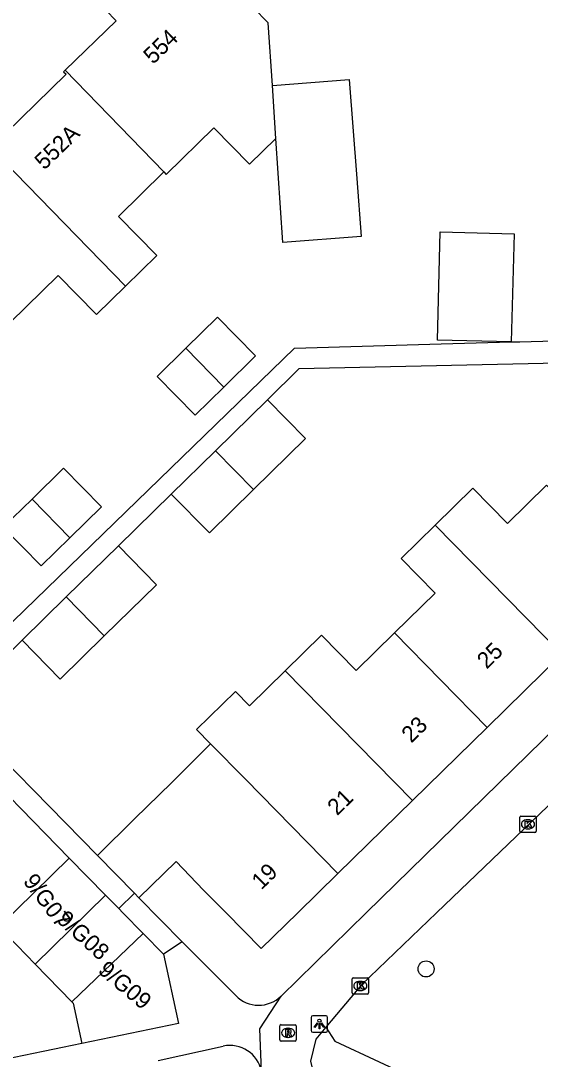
# Model space of a CAD drawing. Extents: x 162880 to 165536, y 384011 to 385179.
# Drawn here: x 164047.4 to 164079, y 384241.1 to 384304.3 of the extents above; entities that cross this region are included whole.
import ezdxf

# ---------------------------------------------------------------- set-up
doc = ezdxf.new("R2010")
doc.units = 0
for name, color, linetype in [('IMGEO_Boom', 7, 'Continuous'), ('IMGEO_Kolk', 7, 'Continuous'), ('IMGEO_Lichtpunt', 7, 'Continuous'), ('IMGEO_Pand', 7, 'Continuous'), ('IMGEO_Pand_nummerreeks', 7, 'Continuous'), ('IMGEO_Rijbaan_lokaal_open', 7, 'Continuous'), ('IMGEO_Rioolput', 7, 'Continuous'), ('IMGEO_Voetpad_halfverhard', 7, 'Continuous'), ('IMGEO_Voetpad_open', 7, 'Continuous')]:
    doc.layers.add(name, color=color, linetype=linetype)

msp = doc.modelspace()

# ---------------------------------------------------------------- linework, layer by layer
at = {"layer": 'IMGEO_Boom'}
msp.add_circle((164072.025, 384246.586), 0.489, dxfattribs=at)
at = {"layer": 'IMGEO_Kolk'}
for p, q in [((164077.725, 384254.97), (164077.725, 384255.822)), ((164077.8, 384255.896), (164078.652, 384255.896)), ((164078.213, 384255.676), (164078.238, 384255.676)), ((164078.726, 384255.822), (164078.726, 384254.97)), ((164078.236, 384255.116), (164078.211, 384255.116)), ((164078.652, 384254.896), (164077.8, 384254.896)), ((164067.522, 384245.125), (164067.522, 384245.977)), ((164067.597, 384246.051), (164068.449, 384246.051)), ((164068.01, 384245.831), (164068.035, 384245.831)), ((164068.523, 384245.977), (164068.523, 384245.125)), ((164068.449, 384245.051), (164067.597, 384245.051)), ((164068.033, 384245.271), (164068.008, 384245.271))]:
    msp.add_line(p, q, dxfattribs=at)
for points in [[(164077.725, 384254.97), (164077.725, 384255.822)], [(164077.8, 384255.896), (164078.652, 384255.896)], [(164078.726, 384255.822), (164078.726, 384254.97)], [(164078.046, 384255.596), (164078.169, 384255.596), (164078.169, 384255.445), (164078.299, 384255.596), (164078.463, 384255.596), (164078.317, 384255.445), (164078.47, 384255.196), (164078.318, 384255.196), (164078.233, 384255.36), (164078.169, 384255.293), (164078.169, 384255.196), (164078.046, 384255.196), (164078.046, 384255.596)], [(164078.652, 384254.896), (164077.8, 384254.896)], [(164067.522, 384245.125), (164067.522, 384245.977)], [(164067.597, 384246.051), (164068.449, 384246.051)], [(164067.843, 384245.751), (164067.966, 384245.751), (164067.966, 384245.6), (164068.096, 384245.751), (164068.26, 384245.751), (164068.114, 384245.6), (164068.267, 384245.351), (164068.115, 384245.351), (164068.03, 384245.515), (164067.966, 384245.448), (164067.966, 384245.351), (164067.843, 384245.351), (164067.843, 384245.751)], [(164068.523, 384245.977), (164068.523, 384245.125)], [(164068.449, 384245.051), (164067.597, 384245.051)]]:
    msp.add_lwpolyline(points, dxfattribs=at)
for centre, start, end in [((164077.802, 384255.82), 91.55205, 178.44795), ((164077.802, 384255.82), 91.55205, 178.44795), ((164078.65, 384255.82), 1.55205, 88.44795), ((164078.65, 384255.82), 1.55205, 88.44795), ((164077.802, 384254.972), 181.55205, 268.44795), ((164077.802, 384254.972), 181.55205, 268.44795), ((164078.65, 384254.972), 271.55205, 358.44795), ((164078.65, 384254.972), 271.55205, 358.44795), ((164067.599, 384245.975), 91.55205, 178.44795), ((164067.599, 384245.975), 91.55205, 178.44795), ((164068.447, 384245.975), 1.55205, 88.44795), ((164068.447, 384245.975), 1.55205, 88.44795), ((164067.599, 384245.127), 181.55205, 268.44795), ((164067.599, 384245.127), 181.55205, 268.44795), ((164068.447, 384245.127), 271.55205, 358.44795), ((164068.447, 384245.127), 271.55205, 358.44795)]:
    msp.add_arc(centre, 0.0765, start, end, dxfattribs=at)
for centre, major_axis, ratio, start_param, end_param in [((164078.212, 384255.396), (-0.387, 0.002), 0.722429, 4.712389, 7.853982), ((164078.237, 384255.396), (-0.39, 0.002), 0.717154, 1.570796, 4.712389), ((164068.009, 384245.551), (-0.387, 0.002), 0.722429, 4.712389, 7.853982), ((164068.034, 384245.551), (-0.39, 0.002), 0.717154, 1.570796, 4.712389)]:
    msp.add_ellipse(centre, major_axis=major_axis, ratio=ratio, start_param=start_param, end_param=end_param, dxfattribs=at)
at = {"layer": 'IMGEO_Lichtpunt'}
for p, q in [((164065.034, 384243.637), (164065.034, 384242.83)), ((164065.034, 384243.637), (164065.034, 384242.83)), ((164065.936, 384243.732), (164065.128, 384243.732)), ((164065.936, 384243.732), (164065.128, 384243.732)), ((164066.03, 384242.83), (164066.03, 384243.637)), ((164066.03, 384242.83), (164066.03, 384243.637)), ((164065.128, 384242.736), (164065.936, 384242.736)), ((164065.128, 384242.736), (164065.936, 384242.736))]:
    msp.add_line(p, q, dxfattribs=at)
for points in [[(164065.408, 384243.301), (164065.447, 384243.273), (164065.259, 384243.011), (164065.221, 384243.038), (164065.408, 384243.301)], [(164065.51, 384243.253), (164065.557, 384243.253), (164065.557, 384242.931), (164065.51, 384242.931), (164065.51, 384243.253)], [(164065.62, 384243.273), (164065.658, 384243.3), (164065.845, 384243.038), (164065.806, 384243.01), (164065.62, 384243.273)]]:
    msp.add_lwpolyline(points, dxfattribs=at)
msp.add_circle((164065.533, 384243.435), 0.0994, dxfattribs=at)
for centre, start, end in [((164065.128, 384243.637), 90, 180), ((164065.128, 384243.637), 90, 180), ((164065.936, 384243.637), 0, 90), ((164065.936, 384243.637), 0, 90), ((164065.128, 384242.83), 180, 270), ((164065.128, 384242.83), 180, 270), ((164065.936, 384242.83), 270, 0), ((164065.936, 384242.83), 270, 360)]:
    msp.add_arc(centre, 0.0946, start, end, dxfattribs=at)
at = {"layer": 'IMGEO_Pand'}
for points in [[(164062.668, 384300.404), (164062.417, 384304.214), (164061.503, 384305.153), (164058.017, 384308.737), (164055.073, 384305.874), (164054.294, 384306.679), (164052.538, 384304.98), (164053.169, 384304.345), (164050.068, 384301.337)], [(164050.068, 384301.337), (164049.966, 384301.238), (164050.119, 384301.08), (164045.521, 384296.61)], [(164050.068, 384301.337), (164056.064, 384295.138)], [(164062.668, 384300.404), (164067.351, 384300.763), (164067.808, 384294.74), (164068.077, 384291.199), (164063.297, 384290.837), (164062.88, 384297.173)], [(164062.88, 384297.173), (164062.668, 384300.404)], [(164056.064, 384295.138), (164056.217, 384294.98), (164059.114, 384297.821), (164061.285, 384295.608), (164062.88, 384297.173)], [(164045.521, 384296.61), (164053.725, 384288.178)], [(164053.725, 384288.178), (164055.631, 384290.048), (164053.299, 384292.425), (164056.064, 384295.138)], [(164077.211, 384284.78), (164072.71, 384284.895), (164072.879, 384291.48), (164077.38, 384291.364), (164077.211, 384284.78)], [(164053.725, 384288.178), (164051.962, 384286.448), (164049.63, 384288.825), (164046.718, 384285.967)], [(164057.407, 384284.393), (164059.329, 384286.279), (164061.64, 384283.924), (164059.708, 384282.029)], [(164059.708, 384282.029), (164057.971, 384280.324), (164055.66, 384282.679), (164057.407, 384284.393)], [(164057.407, 384284.393), (164059.708, 384282.029)], [(164059.21, 384278.151), (164062.376, 384281.256)], [(164062.376, 384281.256), (164064.691, 384278.895), (164061.526, 384275.79)], [(164056.519, 384275.511), (164059.21, 384278.151)], [(164061.526, 384275.79), (164059.21, 384278.151)], [(164048.047, 384275.211), (164049.963, 384277.09), (164052.274, 384274.734), (164050.348, 384272.845)], [(164072.57, 384273.616), (164074.874, 384275.876), (164076.98, 384273.729), (164079.356, 384276.061), (164081.46, 384273.916), (164084.962, 384270.347), (164080.28, 384265.756)], [(164061.526, 384275.79), (164058.835, 384273.15), (164056.519, 384275.511)], [(164050.348, 384272.845), (164048.605, 384271.135), (164046.294, 384273.491), (164048.047, 384275.211)], [(164050.348, 384272.845), (164048.047, 384275.211)], [(164070.096, 384267.053), (164072.57, 384269.481), (164070.503, 384271.588), (164072.57, 384273.616)], [(164072.57, 384273.616), (164080.28, 384265.756)], [(164050.128, 384269.244), (164053.297, 384272.353)], [(164053.297, 384272.353), (164055.612, 384269.992), (164052.444, 384266.884)], [(164047.44, 384266.608), (164050.128, 384269.244)], [(164052.444, 384266.884), (164050.128, 384269.244)], [(164063.45, 384264.748), (164065.659, 384266.915), (164067.766, 384264.768), (164070.096, 384267.053)], [(164070.096, 384267.053), (164075.737, 384261.302)], [(164052.444, 384266.884), (164049.756, 384264.247), (164047.44, 384266.608)], [(164080.28, 384265.756), (164075.737, 384261.302)], [(164058.911, 384260.295), (164058.06, 384261.162), (164060.428, 384263.485), (164061.279, 384262.618), (164063.45, 384264.748)], [(164071.198, 384256.85), (164063.45, 384264.748)], [(164075.737, 384261.302), (164071.198, 384256.85)], [(164043.707, 384260.084), (164043.725, 384260.066), (164050.313, 384253.336)], [(164052.025, 384253.502), (164054.31, 384255.745), (164056.525, 384257.919), (164058.911, 384260.295)], [(164058.911, 384260.295), (164061.027, 384258.138), (164066.658, 384252.399)], [(164071.198, 384256.85), (164066.658, 384252.399)], [(164050.313, 384253.336), (164046.014, 384249.142)], [(164050.313, 384253.336), (164052.518, 384251.083)], [(164054.278, 384251.206), (164052.025, 384253.502)], [(164066.658, 384252.399), (164064.212, 384250), (164061.995, 384247.826), (164059.856, 384250), (164058.488, 384251.391), (164056.809, 384253.14), (164054.553, 384250.926)], [(164052.518, 384251.083), (164048.226, 384246.881)], [(164052.518, 384251.083), (164053.319, 384250.265)], [(164054.278, 384251.206), (164054.553, 384250.926)], [(164053.319, 384250.265), (164053.578, 384250), (164054.812, 384248.74)], [(164046.014, 384249.142), (164048.226, 384246.881)], [(164050.472, 384244.587), (164054.812, 384248.74)], [(164054.812, 384248.74), (164056.043, 384247.482)], [(164056.043, 384247.482), (164056.963, 384243.259), (164051.084, 384242.038)], [(164048.226, 384246.881), (164050.472, 384244.587)], [(164050.472, 384244.587), (164050.546, 384244.511), (164051.084, 384242.038)]]:
    msp.add_lwpolyline(points, dxfattribs=at)
at = {"layer": 'IMGEO_Rijbaan_lokaal_open'}
msp.add_lwpolyline([(164051.084, 384242.038), (164039.286, 384239.612), (164038.275, 384239.297), (164038.104, 384239.136)], dxfattribs=at)
at = {"layer": 'IMGEO_Rioolput'}
for p, q in [((164063.127, 384242.265), (164063.127, 384243.117)), ((164063.202, 384243.191), (164064.054, 384243.191)), ((164064.128, 384243.117), (164064.128, 384242.265)), ((164063.638, 384242.411), (164063.613, 384242.411)), ((164063.615, 384242.971), (164063.64, 384242.971)), ((164064.054, 384242.191), (164063.202, 384242.191))]:
    msp.add_line(p, q, dxfattribs=at)
for points in [[(164063.127, 384242.265), (164063.127, 384243.117)], [(164063.202, 384243.191), (164064.054, 384243.191)], [(164064.128, 384243.117), (164064.128, 384242.265)], [(164063.716, 384242.889), (164063.464, 384242.891), (164063.464, 384242.491)], [(164063.464, 384242.491), (164063.588, 384242.491), (164063.588, 384242.653), (164063.599, 384242.653)], [(164063.642, 384242.81), (164063.588, 384242.81), (164063.588, 384242.729)], [(164063.588, 384242.729), (164063.64, 384242.729)], [(164063.646, 384242.624), (164063.717, 384242.491), (164063.857, 384242.491), (164063.792, 384242.617)], [(164064.054, 384242.191), (164063.202, 384242.191)]]:
    msp.add_lwpolyline(points, dxfattribs=at)
for centre, radius, start, end in [((164063.204, 384243.115), 0.0765, 91.55205, 178.44795), ((164063.204, 384243.115), 0.0765, 91.55205, 178.44795), ((164064.052, 384243.115), 0.0765, 1.55205, 88.44795), ((164064.052, 384243.115), 0.0765, 1.55205, 88.44795), ((164063.598, 384242.6), 0.0533, 26.02933, 88.69889), ((164063.624, 384242.918), 0.19, 274.7715, 282.96867), ((164063.648, 384242.714), 0.0964, 77.00612, 93.18647), ((164063.662, 384242.771), 0.0378, 276.66336, 79.67722), ((164063.715, 384242.779), 0.109, 350.36119, 89.41601), ((164063.713, 384242.779), 0.112, 277.58423, 350.98172), ((164063.697, 384242.564), 0.108, 29.51342, 73.79051), ((164063.204, 384242.267), 0.0765, 181.55205, 268.44795), ((164063.204, 384242.267), 0.0765, 181.55205, 268.44795), ((164064.052, 384242.267), 0.0765, 271.55205, 358.44795), ((164064.052, 384242.267), 0.0765, 271.55205, 358.44795)]:
    msp.add_arc(centre, radius, start, end, dxfattribs=at)
for centre, major_axis, ratio, start_param, end_param in [((164063.614, 384242.691), (-0.387, 0.002), 0.722429, 4.712389, 7.853982), ((164063.639, 384242.691), (-0.39, 0.002), 0.717154, 1.570796, 4.712389)]:
    msp.add_ellipse(centre, major_axis=major_axis, ratio=ratio, start_param=start_param, end_param=end_param, dxfattribs=at)
at = {"layer": 'IMGEO_Voetpad_halfverhard'}
msp.add_lwpolyline([(164065.926, 384243.045), (164066.473, 384242.185), (164074.565, 384238.409)], dxfattribs=at)
at = {"layer": 'IMGEO_Voetpad_open'}
for points in [[(164041.4, 384262.442), (164064.027, 384284.392), (164072.952, 384284.662), (164077.211, 384284.78)], [(164077.211, 384284.78), (164077.726, 384284.794), (164083.317, 384284.95), (164088.338, 384285.009), (164088.288, 384284.403), (164087.526, 384283.655)], [(164087.526, 384283.655), (164064.289, 384283.133), (164062.376, 384281.256)], [(164056.519, 384275.511), (164053.297, 384272.353)], [(164063.201, 384244.93), (164068.383, 384250), (164094.306, 384275.362)], [(164047.44, 384266.608), (164043.225, 384262.473), (164052.025, 384253.502)], [(164080.9, 384257.899), (164072.655, 384250), (164068.089, 384245.625), (164065.926, 384243.045)], [(164053.319, 384250.265), (164054.278, 384251.206)], [(164054.553, 384250.926), (164057.185, 384248.244)], [(164057.185, 384248.244), (164056.043, 384247.482)], [(164057.185, 384248.244), (164060.439, 384244.959)], [(164062.005, 384240.357), (164061.9, 384242.942), (164063.201, 384244.93)], [(164065.926, 384243.045), (164065.316, 384242.317), (164064.991, 384240.969), (164065.064, 384240.618)], [(164055.725, 384241.01), (164059.675, 384241.888)]]:
    msp.add_lwpolyline(points, dxfattribs=at)
for centre, radius, start, end in [((164061.835, 384246.341), 1.964, 224.71954, 314.07733), ((164060.074, 384239.957), 1.972, 11.69837, 101.68527)]:
    msp.add_arc(centre, radius, start, end, dxfattribs=at)

# ---------------------------------------------------------------- texts
at = {"layer": 'IMGEO_Pand_nummerreeks'}
for s, rotation, p in [('554', 44.19223, (164055.412, 384301.651)), ('552A', 44.19223, (164048.79, 384295.214)), ('25', 44.43824, (164075.717, 384264.811)), ('23', 44.43824, (164071.124, 384260.307)), ('21', 44.43861, (164066.611, 384255.882)), ('19', 44.43861, (164062.002, 384251.363)), ('9/G07', 306.9365, (164047.464, 384251.916)), ('9/G08', 317.54383, (164049.488, 384249.505)), ('9/G09', 319.72557, (164051.997, 384246.405))]:
    msp.add_text(s, height=1, rotation=rotation, dxfattribs=at).set_placement(p)

doc.saveas('drawing.dxf')
